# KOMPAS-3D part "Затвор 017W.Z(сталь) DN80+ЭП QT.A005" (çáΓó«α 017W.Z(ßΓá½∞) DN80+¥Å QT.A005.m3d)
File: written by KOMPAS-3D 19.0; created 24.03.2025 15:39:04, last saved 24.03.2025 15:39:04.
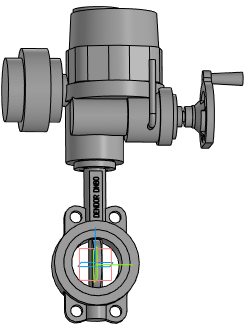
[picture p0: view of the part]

Document properties: Полное имя файла: Затвор 017W.Z(сталь) DN80+ЭП QT.A005.a3d

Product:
- Part/product: Затвор 017W.Z(сталь) DN80+ЭП QT.A005
    Масса: 40.7565

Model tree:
1. Операция без истории:1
